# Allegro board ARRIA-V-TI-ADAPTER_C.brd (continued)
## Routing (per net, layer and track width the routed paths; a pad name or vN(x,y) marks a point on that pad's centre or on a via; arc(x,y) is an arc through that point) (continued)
ADC_A0P: length 187.7
  LAYER6 w0.112: v1(107.96,41.31) 108.44,41.8 112.46,41.8 168.78,98.12 168.78,117.22 168.49,117.51 163.7,117.51 163.58,117.63 163.58,117.94 163.7,118.06 168.49,118.06 168.78,118.35 168.78,118.94 168.49,119.23 163.82,119.23 163.69,119.36 163.69,119.66 163.82,119.79 168.49,119.79 168.78,120.08 168.78,120.67 168.49,120.96 164.12,120.96 164.01,121.07 164.01,121.41 164.12,121.52 168.49,121.52 168.78,121.81 168.78,122.4 168.49,122.69 164.12,122.69 164.01,122.8 164.01,123.13 164.12,123.25 168.49,123.25 168.78,123.54 168.78,124.12 168.49,124.41 164.12,124.41 164.01,124.53 164.01,124.86 164.12,124.97 168.49,124.97 168.78,125.26 168.78,127.84 183.44,142.5 183.44,144.65 v1(183.74,144.95)
  BOTTOM w0.114: v1(107.96,41.31) J3.K25 ; J1.94 183.54,143.9 183.44,144 183.44,144.65 v1(183.74,144.95)
ADC_A1N: length 200.6
  LAYER6 w0.112: v1(106.69,41.31) 107.17,40.83 114.36,40.83 170.81,97.28 170.81,101.79 171.11,102.08 175.64,102.08 175.77,102.21 175.77,102.51 175.64,102.64 171.11,102.64 170.81,102.93 170.81,103.52 171.11,103.81 175.84,103.81 175.97,103.93 175.97,104.24 175.84,104.36 171.11,104.36 170.81,104.65 170.81,105.24 171.11,105.53 175.84,105.53 175.97,105.66 175.97,105.96 175.84,106.09 171.11,106.09 170.81,106.38 170.81,106.97 171.11,107.26 175.84,107.26 175.97,107.39 175.97,107.69 175.84,107.82 171.11,107.82 170.81,108.11 170.81,108.7 171.11,108.99 175.84,108.99 175.97,109.11 175.97,109.42 175.84,109.55 171.11,109.55 170.81,109.84 170.81,110.42 171.11,110.71 175.84,110.71 175.97,110.84 175.97,111.15 175.84,111.27 171.11,111.27 170.81,111.56 170.81,127 180.47,136.65 180.82,136.65 180.94,136.76 180.94,136.92 181.06,137.05 181.37,137.05 181.49,136.92 181.49,136.76 181.61,136.65 183.26,136.65 184.64,138.03 184.64,140.41 v1(184.34,140.71)
  BOTTOM w0.114: v1(106.69,41.31) J3.J25 ; v1(184.34,140.71) 184.64,141.01 184.64,141.16 184.54,141.26 J1.90
ADC_A1P: length 200.6
  LAYER6 w0.112: v1(185.24,140.71) 184.94,140.41 184.94,137.9 183.39,136.35 180.59,136.35 171.12,126.87 171.12,111.69 171.23,111.58 175.97,111.58 176.28,111.27 176.28,110.72 175.97,110.41 171.23,110.41 171.12,110.3 171.12,109.96 171.23,109.85 175.97,109.85 176.28,109.55 176.28,108.99 175.97,108.68 171.23,108.68 171.12,108.57 171.12,108.24 171.23,108.12 175.97,108.12 176.28,107.82 176.28,107.26 175.97,106.96 171.23,106.96 171.12,106.84 171.12,106.51 171.23,106.4 175.97,106.4 176.28,106.09 176.28,105.53 175.97,105.23 171.23,105.23 171.12,105.12 171.12,104.78 171.23,104.67 175.97,104.67 176.28,104.36 176.28,103.81 175.97,103.5 171.23,103.5 171.12,103.39 171.12,103.05 171.23,102.94 175.77,102.94 176.07,102.64 176.07,102.08 175.77,101.77 171.23,101.77 171.12,101.66 171.12,97.16 114.49,40.53 107.17,40.53 v1(106.69,40.04)
  BOTTOM w0.114: J1.88 185.04,141.26 184.94,141.16 184.94,141.01 v1(185.24,140.71) ; v1(106.69,40.04) J3.J24
ADC_A2N: length 213.7
  LAYER6 w0.112: v1(185.84,144.95) 186.14,144.65 186.14,143.28 186.03,143.17 185.86,143.17 185.74,143.04 185.74,142.74 185.86,142.61 186.03,142.61 186.14,142.5 186.14,137.12 181.1,132.08 181.1,127.3 179.32,125.53 179.32,123.6 179.21,123.49 174.03,123.49 173.74,123.2 173.74,122.61 174.03,122.32 179.21,122.32 179.32,122.21 179.32,121.88 179.21,121.77 174.03,121.77 173.74,121.47 173.74,120.89 174.03,120.6 179.21,120.6 179.32,120.48 179.32,120.15 179.21,120.04 174.03,120.04 173.74,119.75 173.74,119.16 174.03,118.87 179.21,118.87 179.32,118.76 179.32,118.42 179.21,118.31 174.03,118.31 173.74,118.02 173.74,117.43 174.03,117.14 179.21,117.14 179.32,117.03 179.32,116.7 179.21,116.58 174.03,116.58 173.74,116.29 173.74,115.71 174.03,115.42 179.21,115.42 179.32,115.3 179.32,114.97 179.21,114.86 175.57,114.86 175.26,114.55 175.26,113.99 175.57,113.69 179.21,113.69 179.32,113.58 179.32,102.54 115.07,38.29 103.36,38.29 v1(102.88,38.77)
  BOTTOM w0.114: J1.84 186.04,143.9 186.14,144 186.14,144.65 v1(185.84,144.95) ; v1(102.88,38.77) J3.F23
ADC_A2P: length 213.7
  LAYER6 w0.112: v1(102.88,37.5) 103.36,37.99 115.2,37.99 179.63,102.41 179.63,113.7 179.34,113.99 175.69,113.99 175.56,114.12 175.56,114.42 175.69,114.55 179.34,114.55 179.63,114.84 179.63,115.43 179.34,115.72 174.15,115.72 174.04,115.83 174.04,116.17 174.15,116.28 179.34,116.28 179.63,116.57 179.63,117.16 179.34,117.45 174.15,117.45 174.04,117.56 174.04,117.89 174.15,118.01 179.34,118.01 179.63,118.3 179.63,118.88 179.34,119.17 174.15,119.17 174.04,119.29 174.04,119.62 174.15,119.73 179.34,119.73 179.63,120.02 179.63,120.61 179.34,120.9 174.15,120.9 174.04,121.01 174.04,121.35 174.15,121.46 179.34,121.46 179.63,121.75 179.63,122.34 179.34,122.63 174.15,122.63 174.04,122.74 174.04,123.08 174.15,123.19 179.34,123.19 179.63,123.48 179.63,125.4 181.41,127.18 181.41,131.95 186.44,136.99 186.44,144.65 v1(186.74,144.95)
  BOTTOM w0.114: J1.82 186.54,143.9 186.44,144 186.44,144.65 v1(186.74,144.95) ; v1(102.88,37.5) J3.F22
ADC_A3N: length 212.5
  LAYER6 w0.112: v1(187.34,140.71) 187.64,140.41 187.64,133.02 187.53,132.91 187.38,132.91 187.25,132.78 187.25,132.48 187.38,132.35 187.53,132.35 187.64,132.24 187.64,128.13 181.74,122.22 181.74,103.49 182.03,103.2 182.74,103.2 182.87,103.08 182.87,102.77 182.74,102.64 182.03,102.64 181.74,102.35 181.74,101.7 180.99,100.96 180.99,100.54 183.03,98.5 183.03,98.32 182.82,98.11 182.64,98.11 180.6,100.15 180.18,100.15 179.77,99.73 179.77,99.32 181.75,97.34 181.75,97.16 181.53,96.95 181.35,96.95 179.37,98.93 178.96,98.93 178.55,98.51 178.55,98.1 180.26,96.39 180.26,96.23 180.02,95.99 179.86,95.99 178.15,97.7 177.74,97.7 177.32,97.29 177.32,96.88 179.03,95.17 179.03,95.01 178.8,94.77 178.64,94.77 176.93,96.48 176.52,96.48 176.1,96.07 176.1,95.66 177.81,93.95 177.81,93.79 177.57,93.55 177.42,93.55 175.71,95.26 175.3,95.26 174.88,94.84 174.88,94.43 176.59,92.72 176.59,92.57 176.35,92.33 176.19,92.33 174.48,94.04 174.07,94.04 173.66,93.62 173.66,93.21 175.37,91.5 175.37,91.34 175.13,91.11 174.97,91.11 173.26,92.82 172.85,92.82 172.44,92.4 172.44,91.99 174.14,90.28 174.14,90.12 173.91,89.88 173.75,89.88 172.04,91.59 171.63,91.59 171.21,91.18 171.21,90.77 172.92,89.06 172.92,88.9 172.68,88.66 172.53,88.66 170.82,90.37 170.41,90.37 169.99,89.96 169.99,89.54 171.7,87.83 171.7,87.68 171.46,87.44 171.3,87.44 169.59,89.15 169.18,89.15 168.77,88.73 168.77,88.32 170.48,86.61 170.48,86.45 170.24,86.22 170.08,86.22 168.37,87.93 167.96,87.93 117.06,37.02 102.09,37.02 v1(101.61,37.5)
  BOTTOM w0.114: v1(101.61,37.5) J3.E22 ; J1.78 187.54,141.26 187.64,141.16 187.64,141.01 v1(187.34,140.71)
ADC_A3P: length 212.5
  LAYER6 w0.112: v1(188.24,140.71) 187.94,140.41 187.94,128 182.04,122.1 182.04,103.62 182.15,103.51 182.87,103.51 183.17,103.2 183.17,102.64 182.87,102.34 182.15,102.34 182.04,102.23 182.04,101.58 181.3,100.83 181.3,100.67 183.34,98.63 183.34,98.2 182.94,97.8 182.51,97.8 180.47,99.84 180.31,99.84 180.07,99.61 180.07,99.45 182.05,97.47 182.05,97.04 181.66,96.64 181.22,96.64 179.25,98.62 179.09,98.62 178.85,98.38 178.85,98.23 180.56,96.52 180.56,96.11 180.14,95.69 179.73,95.69 178.02,97.4 177.87,97.4 177.63,97.16 177.63,97 179.34,95.29 179.34,94.88 178.92,94.47 178.51,94.47 176.8,96.18 176.64,96.18 176.41,95.94 176.41,95.78 178.12,94.07 178.12,93.66 177.7,93.24 177.29,93.24 175.58,94.95 175.42,94.95 175.18,94.72 175.18,94.56 176.89,92.85 176.89,92.44 176.48,92.02 176.07,92.02 174.36,93.73 174.2,93.73 173.96,93.5 173.96,93.34 175.67,91.63 175.67,91.22 175.26,90.8 174.84,90.8 173.14,92.51 172.98,92.51 172.74,92.27 172.74,92.12 174.45,90.41 174.45,89.99 174.03,89.58 173.62,89.58 171.91,91.29 171.75,91.29 171.52,91.05 171.52,90.89 173.23,89.18 173.23,88.77 172.81,88.36 172.4,88.36 170.69,90.07 170.53,90.07 170.3,89.83 170.3,89.67 172.01,87.96 172.01,87.55 171.59,87.13 171.18,87.13 169.47,88.84 169.31,88.84 169.07,88.61 169.07,88.45 170.78,86.74 170.78,86.33 170.37,85.91 169.96,85.91 168.25,87.62 168.09,87.62 117.18,36.72 102.09,36.72 v1(101.61,36.23)
  BOTTOM w0.114: v1(101.61,36.23) J3.E21 ; J1.76 188.04,141.26 187.94,141.16 187.94,141.01 v1(188.24,140.71)
ADC_A4N: length 201.4
  LAYER6 w0.112: v1(100.34,20.99) 100.82,20.51 101.9,20.51 102.11,20.71 102.11,23.93 102.49,24.31 114.3,24.31 190.45,100.46 190.45,101.54 190.34,101.65 186.06,101.65 185.75,101.95 185.75,102.51 186.06,102.82 190.34,102.82 190.45,102.93 190.45,103.26 190.34,103.38 186.06,103.38 185.75,103.68 185.75,104.24 186.06,104.55 190.34,104.55 190.45,104.66 190.45,104.99 190.34,105.1 185.93,105.1 185.62,105.41 185.62,105.97 185.93,106.27 190.34,106.27 190.45,106.38 190.45,131.62 189.14,132.93 189.14,142.53 189.03,142.64 188.87,142.64 188.75,142.77 188.75,143.08 188.87,143.2 189.03,143.2 189.14,143.31 189.14,144.65 v1(188.84,144.95)
  BOTTOM w0.114: v1(100.34,20.99) J3.D9 ; J1.72 189.04,143.9 189.14,144 189.14,144.65 v1(188.84,144.95)
ADC_A4P: length 201.4
  LAYER6 w0.112: v1(100.34,19.72) 100.82,20.21 102.03,20.21 102.41,20.59 102.41,23.8 102.62,24 114.43,24 190.75,100.33 190.75,101.66 190.46,101.95 186.18,101.95 186.06,102.08 186.06,102.39 186.18,102.51 190.46,102.51 190.75,102.8 190.75,103.39 190.46,103.68 186.18,103.68 186.06,103.81 186.06,104.11 186.18,104.24 190.46,104.24 190.75,104.53 190.75,105.12 190.46,105.41 186.06,105.41 185.93,105.54 185.93,105.84 186.06,105.97 190.46,105.97 190.75,106.26 190.75,131.75 189.44,133.06 189.44,144.65 v1(189.74,144.95)
  BOTTOM w0.114: v1(100.34,19.72) J3.D8 ; v1(189.74,144.95) 189.44,144.65 189.44,144 189.54,143.9 J1.70
ADC_A5N: length 194.8
  LAYER6 w0.112: v1(104.15,22.26) 104.63,21.78 115.76,21.78 171.74,77.76 172.15,77.76 173.13,76.77 173.31,76.77 173.53,76.98 173.53,77.16 172.54,78.15 172.54,78.56 172.96,78.98 173.37,78.98 175.03,77.32 175.19,77.32 175.42,77.56 175.42,77.71 173.76,79.37 173.76,79.78 174.18,80.2 174.59,80.2 176.25,78.54 176.41,78.54 176.65,78.78 176.65,78.94 174.99,80.6 174.99,81.01 175.4,81.42 175.81,81.42 177.47,79.76 177.63,79.76 177.87,80 177.87,80.16 176.21,81.82 176.21,82.23 176.62,82.64 177.04,82.64 178.69,80.99 178.85,80.99 179.09,81.22 179.09,81.38 177.43,83.04 177.43,83.45 177.85,83.87 178.26,83.87 179.92,82.21 180.07,82.21 180.31,82.45 180.31,82.6 178.65,84.26 178.65,84.67 192.1,98.12 192.1,133.22 191.99,133.33 191.83,133.33 191.71,133.46 191.71,133.76 191.83,133.89 191.99,133.89 192.1,134 192.1,134.49 190.64,135.95 190.64,140.41 v1(190.34,140.71)
  BOTTOM w0.114: v1(104.15,22.26) J3.G10 ; J1.66 190.54,141.26 190.64,141.16 190.64,141.01 v1(190.34,140.71)
ADC_A5P: length 194.8
  LAYER6 w0.112: v1(104.15,20.99) 104.63,21.48 115.89,21.48 171.86,77.45 172.02,77.45 173.01,76.46 173.44,76.46 173.83,76.86 173.83,77.29 172.85,78.28 172.85,78.44 173.08,78.67 173.24,78.67 174.9,77.01 175.31,77.01 175.73,77.43 175.73,77.84 174.07,79.5 174.07,79.66 174.31,79.9 174.46,79.9 176.12,78.24 176.53,78.24 176.95,78.65 176.95,79.06 175.29,80.72 175.29,80.88 175.53,81.12 175.69,81.12 177.35,79.46 177.76,79.46 178.17,79.88 178.17,80.29 176.51,81.94 176.51,82.1 176.75,82.34 176.91,82.34 178.57,80.68 178.98,80.68 179.4,81.1 179.4,81.51 177.74,83.17 177.74,83.32 177.97,83.56 178.13,83.56 179.79,81.9 180.2,81.9 180.62,82.32 180.62,82.73 178.96,84.39 178.96,84.55 192.41,97.99 192.41,134.62 190.94,136.08 190.94,140.41 v1(191.24,140.71)
  BOTTOM w0.114: v1(104.15,20.99) J3.G9 ; J1.64 191.04,141.26 190.94,141.16 190.94,141.01 v1(191.24,140.71)
ADC_A6N: length 202.7
  LAYER6 w0.112: v1(105.42,19.72) 105.9,19.24 106.98,19.24 107.19,19.44 107.19,20.14 107.55,20.5 123.47,20.5 187.03,84.06 187.03,84.22 185.76,85.48 185.76,85.92 186.16,86.31 186.59,86.31 187.86,85.04 188.02,85.04 188.25,85.28 188.25,85.44 186.71,86.98 186.71,87.39 187.12,87.81 187.53,87.81 189.08,86.27 189.24,86.27 189.47,86.5 189.47,86.66 187.93,88.21 187.93,88.62 188.35,89.03 188.76,89.03 190.3,87.49 190.46,87.49 190.7,87.72 190.7,87.88 189.15,89.43 189.15,89.84 189.57,90.25 189.98,90.25 191.52,88.71 191.68,88.71 191.92,88.95 191.92,89.11 190.37,90.65 190.37,91.06 190.79,91.48 191.2,91.48 192.75,89.93 192.9,89.93 194.06,91.08 194.06,140.46 196.09,142.49 196.4,142.49 196.51,142.61 196.51,142.76 196.64,142.89 196.94,142.89 197.07,142.76 197.07,142.61 197.18,142.49 197.61,142.49 199.14,144.02 199.14,144.65 v1(198.84,144.95)
  BOTTOM w0.114: v1(198.84,144.95) 199.14,144.65 199.14,144 199.04,143.9 J1.52 ; v1(105.42,19.72) J3.H8
ADC_A6P: length 202.7
  LAYER6 w0.112: v1(199.74,144.95) 199.44,144.65 199.44,143.89 197.74,142.19 196.21,142.19 194.36,140.34 194.36,90.96 193.03,89.63 192.62,89.63 191.08,91.17 190.92,91.17 190.68,90.93 190.68,90.78 192.22,89.23 192.22,88.82 191.81,88.41 191.4,88.41 189.85,89.95 189.7,89.95 189.46,89.71 189.46,89.55 191,88.01 191,87.6 190.59,87.18 190.18,87.18 188.63,88.73 188.47,88.73 188.23,88.49 188.23,88.33 189.78,86.79 189.78,86.38 189.36,85.96 188.95,85.96 187.41,87.51 187.25,87.51 187.01,87.27 187.01,87.11 188.56,85.56 188.56,85.15 188.14,84.74 187.73,84.74 186.46,86.01 186.28,86.01 186.07,85.79 186.07,85.61 187.34,84.34 187.34,83.93 123.6,20.19 107.67,20.19 107.49,20.01 107.49,19.32 107.11,18.94 105.9,18.94 v1(105.42,18.45)
  BOTTOM w0.114: v1(199.74,144.95) 199.44,144.65 199.44,144 199.54,143.9 J1.50 ; v1(105.42,18.45) J3.H7
ADC_A7N: length 183.3
  LAYER6 w0.112: v1(200.34,140.71) 200.64,140.41 200.64,140.19 199.14,138.68 199.14,137.92 196.92,135.71 196.76,135.71 196.65,135.82 196.47,135.82 196.26,135.6 196.26,135.42 196.37,135.31 196.37,135.15 195.58,134.37 195.58,91.7 195.87,91.41 196.79,91.41 196.91,91.29 196.91,90.98 196.79,90.85 195.87,90.85 195.58,90.56 195.58,89.92 194.64,88.98 194.64,88.57 195.41,87.8 195.41,87.64 195.17,87.4 195.02,87.4 194.25,88.17 193.83,88.17 193.42,87.75 193.42,87.34 194.19,86.57 194.19,86.42 193.95,86.18 193.79,86.18 193.02,86.95 192.61,86.95 192.2,86.53 192.2,86.12 192.97,85.35 192.97,85.19 192.73,84.96 192.57,84.96 191.8,85.73 191.39,85.73 124.9,19.24 108.44,19.24 v1(107.96,19.72)
  BOTTOM w0.114: v1(200.34,140.71) 200.64,141.01 200.64,141.16 200.54,141.26 J1.46 ; v1(107.96,19.72) J3.K8
ADC_A7P: length 183.3
  LAYER6 w0.112: v1(201.24,140.71) 200.94,140.41 200.94,140.06 199.44,138.56 199.44,137.8 195.88,134.24 195.88,91.83 196,91.72 196.91,91.72 197.22,91.41 197.22,90.85 196.91,90.55 196,90.55 195.88,90.44 195.88,89.79 194.95,88.85 194.95,88.69 195.72,87.92 195.72,87.51 195.3,87.1 194.89,87.1 194.12,87.87 193.96,87.87 193.72,87.63 193.72,87.47 194.49,86.7 194.49,86.29 194.08,85.87 193.67,85.87 192.9,86.64 192.74,86.64 192.5,86.41 192.5,86.25 193.27,85.48 193.27,85.07 192.86,84.65 192.44,84.65 191.67,85.42 191.52,85.42 125.03,18.94 108.44,18.94 v1(107.96,18.45)
  BOTTOM w0.114: J1.44 201.04,141.26 200.94,141.16 200.94,141.01 v1(201.24,140.71) ; v1(107.96,18.45) J3.K7
ADC_A8N: length 184.9
  LAYER6 w0.112: v1(201.84,144.95) 202.14,144.65 202.14,142.9 202.03,142.79 201.88,142.79 201.75,142.66 201.75,142.36 201.88,142.23 202.03,142.23 202.14,142.12 202.14,137.55 200.61,136.02 200.61,134.62 199.21,133.22 199.21,86.39 130.8,17.97 107.17,17.97 v1(106.69,18.45)
  BOTTOM w0.114: v1(201.84,144.95) 202.14,144.65 202.14,144 202.04,143.9 J1.40 ; v1(106.69,18.45) J3.J7
ADC_A8P: length 184.9
  LAYER6 w0.112: v1(202.74,144.95) 202.44,144.65 202.44,137.42 200.91,135.89 200.91,134.49 199.52,133.1 199.52,86.26 130.92,17.67 107.17,17.67 v1(106.69,17.18)
  BOTTOM w0.114: J1.38 202.54,143.9 202.44,144 202.44,144.65 v1(202.74,144.95) ; v1(106.69,17.18) J3.J6
ADC_A9N: length 187.8
  LAYER6 w0.112: v1(203.34,140.71) 203.64,140.41 203.64,136.79 203.53,136.68 203.38,136.68 203.25,136.55 203.25,136.24 203.38,136.12 203.53,136.12 203.64,136.01 203.64,134.81 202.13,133.3 202.13,84.38 134.26,16.51 107.34,16.51 107.16,16.69 106.48,16.69 106.22,16.94 106.22,16.99 106.22,16.99 106.22,17.63 105.88,17.97 104.63,17.97 v1(104.15,18.45)
  BOTTOM w0.114: v1(203.34,140.71) 203.64,141.01 203.64,141.16 203.54,141.26 J1.34 ; v1(104.15,18.45) J3.G7
ADC_A9P: length 187.8
  LAYER6 w0.112: v1(204.24,140.71) 203.94,140.41 203.94,134.68 202.44,133.17 202.44,84.25 134.39,16.21 107.21,16.21 107.03,16.38 106.35,16.38 105.92,16.82 105.92,16.86 105.92,16.86 105.92,17.5 105.75,17.67 104.63,17.67 v1(104.15,17.18)
  BOTTOM w0.114: v1(204.24,140.71) 203.94,141.01 203.94,141.16 204.04,141.26 J1.32 ; v1(104.15,17.18) J3.G6
ADC_A10N: length 197.9
  LAYER6 w0.112: v1(204.84,144.95) 205.14,144.65 205.14,142.81 205.03,142.7 204.88,142.7 204.75,142.57 204.75,142.27 204.88,142.14 205.03,142.14 205.14,142.03 205.14,137.51 206.32,136.32 206.32,134.11 205.14,132.93 205.14,82.2 138.37,15.43 103.36,15.43 v1(102.88,15.91)
  BOTTOM w0.114: J1.28 205.04,143.9 205.14,144 205.14,144.65 v1(204.84,144.95) ; v1(102.88,15.91) J3.F5
ADC_A10P: length 197.9
  LAYER6 w0.112: v1(205.74,144.95) 205.44,144.65 205.44,137.63 206.63,136.45 206.63,133.99 205.44,132.8 205.44,82.08 138.49,15.13 103.36,15.13 v1(102.88,14.64)
  BOTTOM w0.114: J1.26 205.54,143.9 205.44,144 205.44,144.65 v1(205.74,144.95) ; v1(102.88,14.64) J3.F4
ADC_A11N: length 197.9
  LAYER6 w0.112: v1(101.61,13.37) 102.09,12.89 108.32,12.89 109.52,14.1 140.16,14.1 207.72,81.66 207.72,134.53 207.61,134.65 207.45,134.65 207.33,134.77 207.33,135.08 207.45,135.21 207.61,135.21 207.72,135.32 207.72,136.83 206.64,137.91 206.64,140.41 v1(206.34,140.71)
  BOTTOM w0.114: v1(206.34,140.71) 206.64,141.01 206.64,141.16 206.54,141.26 J1.22 ; v1(101.61,13.37) J3.E3
ADC_A11P: length 197.9
  LAYER6 w0.112: v1(101.61,12.1) 102.09,12.59 108.45,12.59 109.65,13.79 140.28,13.79 208.03,81.53 208.03,136.96 206.94,138.04 206.94,140.41 v1(207.24,140.71)
  BOTTOM w0.114: J1.20 207.04,141.26 206.94,141.16 206.94,141.01 v1(207.24,140.71) ; v1(101.61,12.1) J3.E2
ADC_B0N: length 210.6
  TOP w0.114: v1(206.34,132.84) 206.64,132.54 206.64,132.01 206.52,131.89 206.38,131.89 206.25,131.76 206.25,131.45 206.38,131.32 206.52,131.32 206.64,131.21 206.64,116.33 205.75,115.44 185.88,115.44 178.94,108.51 178.94,101.28 179.24,100.99 182.09,100.99 182.22,100.86 182.22,100.55 182.09,100.42 179.24,100.42 178.94,100.13 178.94,99.53 179.24,99.24 182.84,99.24 182.96,99.12 182.96,98.78 182.84,98.67 179.24,98.67 178.94,98.37 178.94,97.78 179.24,97.49 182.84,97.49 182.96,97.37 182.96,97.03 182.84,96.91 179.24,96.91 178.94,96.62 178.94,96.03 179.24,95.73 182.84,95.73 182.96,95.62 182.96,95.28 182.84,95.16 179.24,95.16 178.94,94.87 178.94,94.27 179.24,93.98 182.84,93.98 182.96,93.87 182.96,93.52 182.84,93.41 179.24,93.41 178.94,93.12 178.94,78.66 142.38,42.1 103.36,42.1 v1(102.88,42.58)
  BOTTOM w0.114: v1(102.88,42.58) J3.F26 ; v1(206.34,132.84) 206.64,133.14 206.64,135.42 206.54,135.52 J1.21
ADC_B0P: length 210.6
  TOP w0.114: v1(102.88,41.31) 103.36,41.8 142.51,41.8 179.25,78.54 179.25,92.99 179.36,93.1 182.97,93.1 183.26,93.4 183.26,93.99 182.97,94.29 179.36,94.29 179.25,94.4 179.25,94.74 179.36,94.86 182.97,94.86 183.26,95.15 183.26,95.75 182.97,96.04 179.36,96.04 179.25,96.15 179.25,96.5 179.36,96.61 182.97,96.61 183.26,96.9 183.26,97.5 182.97,97.79 179.36,97.79 179.25,97.91 179.25,98.25 179.36,98.36 182.97,98.36 183.26,98.65 183.26,99.25 182.97,99.54 179.36,99.54 179.25,99.66 179.25,100 179.36,100.11 182.22,100.11 182.52,100.42 182.52,100.99 182.22,101.3 179.36,101.3 179.25,101.41 179.25,108.38 186,115.14 205.88,115.14 206.94,116.2 206.94,132.54 v1(207.24,132.84)
  BOTTOM w0.114: J1.19 207.04,135.52 206.94,135.42 206.94,133.14 v1(207.24,132.84) ; v1(102.88,41.31) J3.F25
ADC_B1N: length 211.7
  TOP w0.114: v1(204.84,134.75) 205.14,134.45 205.14,134.03 205.02,133.92 204.88,133.92 204.75,133.79 204.75,133.47 204.88,133.34 205.02,133.34 205.14,133.23 205.14,117.73 204.76,117.35 183.85,117.35 171.02,104.52 171.02,100.1 171.31,99.81 173.69,99.81 173.81,99.68 173.81,99.36 173.69,99.24 171.31,99.24 171.02,98.94 171.02,98.35 171.31,98.06 175.35,98.06 175.46,97.94 175.46,97.6 175.35,97.48 171.31,97.48 171.02,97.19 171.02,96.6 171.31,96.3 175.35,96.3 175.46,96.19 175.46,95.85 175.35,95.73 171.31,95.73 171.02,95.44 171.02,94.84 171.31,94.55 175.35,94.55 175.46,94.44 175.46,94.09 175.35,93.98 171.31,93.98 171.02,93.69 171.02,93.09 171.31,92.8 175.35,92.8 175.46,92.68 175.46,92.34 175.35,92.23 171.31,92.23 171.02,91.93 171.02,76.07 138.33,43.38 106.43,43.38 106.22,43.59 106.22,44.3 105.88,44.64 102.09,44.64 v1(101.61,45.12)
  BOTTOM w0.114: J1.27 205.04,135.52 205.14,135.42 205.14,135.05 v1(204.84,134.75) ; v1(101.61,45.12) J3.E28
ADC_B1P: length 211.7
  TOP w0.114: v1(205.74,134.75) 205.44,134.45 205.44,117.6 204.88,117.04 183.97,117.04 171.32,104.39 171.32,100.23 171.44,100.11 173.81,100.11 174.12,99.81 174.12,99.24 173.81,98.93 171.44,98.93 171.32,98.82 171.32,98.48 171.44,98.36 175.48,98.36 175.77,98.07 175.77,97.47 175.48,97.18 171.44,97.18 171.32,97.07 171.32,96.72 171.44,96.61 175.48,96.61 175.77,96.32 175.77,95.72 175.48,95.43 171.44,95.43 171.32,95.31 171.32,94.97 171.44,94.86 175.48,94.86 175.77,94.56 175.77,93.97 175.48,93.67 171.44,93.67 171.32,93.56 171.32,93.22 171.44,93.1 175.48,93.1 175.77,92.81 175.77,92.21 175.48,91.92 171.44,91.92 171.32,91.81 171.32,75.95 138.46,43.08 106.3,43.08 105.92,43.46 105.92,44.17 105.75,44.34 102.09,44.34 v1(101.61,43.85)
  BOTTOM w0.114: v1(101.61,43.85) J3.E27 ; v1(205.74,134.75) 205.44,135.05 205.44,135.42 205.54,135.52 J1.25
ADC_B2N: length 204.1
  TOP w0.114: v1(106.69,45.12) 107.17,44.64 134.81,44.64 168.27,78.11 168.27,80.3 168.16,80.42 164.08,80.42 163.78,80.72 163.78,81.29 164.08,81.6 168.16,81.6 168.27,81.71 168.27,82.06 168.16,82.17 164.08,82.17 163.78,82.48 163.78,83.05 164.08,83.35 168.16,83.35 168.27,83.47 168.27,83.81 168.16,83.92 164.08,83.92 163.78,84.23 163.78,84.8 164.08,85.1 168.16,85.1 168.27,85.22 168.27,85.56 168.16,85.68 164.08,85.68 163.78,85.98 163.78,86.55 164.08,86.86 168.16,86.86 168.27,86.97 168.27,87.31 168.16,87.43 164.92,87.43 164.62,87.73 164.62,88.3 164.92,88.61 168.16,88.61 168.27,88.72 168.27,105.84 181.69,119.25 203.07,119.25 203.64,119.82 203.64,130.99 203.52,131.11 203.37,131.11 203.24,131.23 203.24,131.55 203.37,131.68 203.52,131.68 203.64,131.79 203.64,132.54 v1(203.34,132.84)
  BOTTOM w0.114: v1(203.34,132.84) 203.64,133.14 203.64,135.42 203.54,135.52 J1.33 ; v1(106.69,45.12) J3.J28
ADC_B2P: length 204.1
  TOP w0.114: v1(106.69,43.85) 107.17,44.34 134.94,44.34 168.58,77.98 168.58,80.43 168.29,80.72 164.21,80.72 164.08,80.85 164.08,81.17 164.21,81.29 168.29,81.29 168.58,81.59 168.58,82.18 168.29,82.48 164.21,82.48 164.08,82.6 164.08,82.92 164.21,83.05 168.29,83.05 168.58,83.34 168.58,83.94 168.29,84.23 164.21,84.23 164.08,84.36 164.08,84.67 164.21,84.8 168.29,84.8 168.58,85.09 168.58,85.69 168.29,85.98 164.21,85.98 164.08,86.11 164.08,86.43 164.21,86.55 168.29,86.55 168.58,86.85 168.58,87.44 168.29,87.73 165.05,87.73 164.92,87.86 164.92,88.18 165.05,88.31 168.29,88.31 168.58,88.6 168.58,105.71 181.81,118.95 203.2,118.95 203.94,119.69 203.94,132.54 v1(204.24,132.84)
  BOTTOM w0.114: v1(106.69,43.85) J3.J27 ; v1(204.24,132.84) 203.94,133.14 203.94,135.42 204.04,135.52 J1.31
ADC_B3N: length 194.1
  TOP w0.114: v1(107.96,46.39) 108.44,45.91 131,45.91 158.88,73.79 158.88,92.31 159.17,92.6 161.72,92.6 161.85,92.73 161.85,93.05 161.72,93.17 159.17,93.17 158.88,93.47 158.88,94.06 159.17,94.36 164.17,94.36 164.29,94.47 164.29,94.81 164.17,94.93 159.17,94.93 158.88,95.22 158.88,95.82 159.17,96.11 164.17,96.11 164.29,96.22 164.29,96.57 164.17,96.68 159.17,96.68 158.88,96.97 158.88,97.57 159.17,97.86 164.17,97.86 164.29,97.98 164.29,98.32 164.17,98.43 159.17,98.43 158.88,98.72 158.88,99.87 180.16,121.16 201.17,121.16 202.14,122.13 202.14,133.38 202.02,133.49 201.87,133.49 201.74,133.62 201.74,133.94 201.87,134.07 202.02,134.07 202.14,134.18 202.14,134.45 v1(201.84,134.75)
  BOTTOM w0.114: J1.39 202.04,135.52 202.14,135.42 202.14,135.05 v1(201.84,134.75) ; v1(107.96,46.39) J3.K29
ADC_B3P: length 194.1
  TOP w0.114: v1(202.74,134.75) 202.44,134.45 202.44,122 201.29,120.85 180.29,120.85 159.18,99.75 159.18,98.85 159.3,98.74 164.3,98.74 164.59,98.44 164.59,97.85 164.3,97.56 159.3,97.56 159.18,97.44 159.18,97.1 159.3,96.98 164.3,96.98 164.59,96.69 164.59,96.1 164.3,95.8 159.3,95.8 159.18,95.69 159.18,95.35 159.3,95.23 164.3,95.23 164.59,94.94 164.59,94.34 164.3,94.05 159.3,94.05 159.18,93.94 159.18,93.59 159.3,93.48 161.85,93.48 162.15,93.17 162.15,92.6 161.85,92.3 159.3,92.3 159.18,92.18 159.18,73.66 131.13,45.61 108.44,45.61 v1(107.96,45.12)
  BOTTOM w0.114: v1(107.96,45.12) J3.K28 ; v1(202.74,134.75) 202.44,135.05 202.44,135.42 202.54,135.52 J1.37
ADC_B4N: length 213.6
  TOP w0.114: v1(200.34,132.84) 200.64,132.54 200.64,123.93 199.77,123.06 177.75,123.06 156.08,101.4 156.08,96.77 155.97,96.66 155.82,96.66 155.69,96.53 155.69,96.21 155.82,96.09 155.97,96.09 156.08,95.97 156.08,95.58 155.97,95.47 153.07,95.47 152.78,95.17 152.78,94.58 153.07,94.28 155.97,94.28 156.08,94.17 156.08,93.83 155.97,93.71 153.07,93.71 152.78,93.42 152.78,92.82 153.07,92.53 155.97,92.53 156.08,92.42 156.08,92.07 155.97,91.96 153.07,91.96 152.78,91.67 152.78,91.07 153.07,90.78 155.97,90.78 156.08,90.66 156.08,90.32 155.97,90.21 153.07,90.21 152.78,89.91 152.78,89.32 153.07,89.03 155.97,89.03 156.08,88.91 156.08,88.57 155.97,88.45 153.07,88.45 152.78,88.16 152.78,87.57 153.07,87.27 155.97,87.27 156.08,87.16 156.08,86.82 155.97,86.7 153.07,86.7 152.78,86.41 152.78,85.81 153.07,85.52 155.97,85.52 156.08,85.41 156.08,85.06 155.97,84.95 153.07,84.95 152.78,84.66 152.78,84.06 153.07,83.77 155.97,83.77 156.08,83.65 156.08,83.31 155.97,83.2 153.07,83.2 152.78,82.9 152.78,82.31 153.07,82.02 155.97,82.02 156.08,81.9 156.08,81.56 155.97,81.44 154.13,81.44 153.82,81.14 153.82,80.57 154.13,80.26 155.97,80.26 156.08,80.15 156.08,75.31 127.94,47.17 106.25,47.17 105.92,46.84 105.92,46.16 105.66,45.91 103.36,45.91 v1(102.88,46.39)
  BOTTOM w0.114: v1(102.88,46.39) J3.F29 ; J1.45 200.54,135.52 200.64,135.42 200.64,133.14 v1(200.34,132.84)
ADC_B4P: length 213.6
  TOP w0.114: v1(201.24,132.84) 200.94,132.54 200.94,123.8 199.9,122.76 177.88,122.76 156.39,101.27 156.39,95.45 156.1,95.16 153.2,95.16 153.09,95.05 153.09,94.7 153.2,94.59 156.1,94.59 156.39,94.3 156.39,93.7 156.1,93.41 153.2,93.41 153.09,93.29 153.09,92.95 153.2,92.84 156.1,92.84 156.39,92.54 156.39,91.95 156.1,91.66 153.2,91.66 153.09,91.54 153.09,91.2 153.2,91.08 156.1,91.08 156.39,90.79 156.39,90.2 156.1,89.9 153.2,89.9 153.09,89.79 153.09,89.45 153.2,89.33 156.1,89.33 156.39,89.04 156.39,88.44 156.1,88.15 153.2,88.15 153.09,88.04 153.09,87.69 153.2,87.58 156.1,87.58 156.39,87.29 156.39,86.69 156.1,86.4 153.2,86.4 153.09,86.28 153.09,85.94 153.2,85.83 156.1,85.83 156.39,85.53 156.39,84.94 156.1,84.64 153.2,84.64 153.09,84.53 153.09,84.19 153.2,84.07 156.1,84.07 156.39,83.78 156.39,83.18 156.1,82.89 153.2,82.89 153.09,82.78 153.09,82.43 153.2,82.32 156.1,82.32 156.39,82.03 156.39,81.43 156.1,81.14 154.25,81.14 154.13,81.01 154.13,80.7 154.25,80.57 156.1,80.57 156.39,80.28 156.39,75.18 128.07,46.86 106.37,46.86 106.22,46.71 106.22,46.04 105.79,45.61 103.36,45.61 v1(102.88,45.12)
  BOTTOM w0.114: v1(201.24,132.84) 200.94,133.14 200.94,135.42 201.04,135.52 J1.43 ; v1(102.88,45.12) J3.F28
ADC_B5N: length 207.1
  TOP w0.114: v1(198.84,134.75) 199.14,134.45 199.14,133.97 199.02,133.85 198.87,133.85 198.74,133.73 198.74,133.41 198.87,133.28 199.02,133.28 199.14,133.17 199.14,132.13 198.76,131.75 195,131.75 194.69,131.44 194.69,130.61 195,130.3 199.01,130.3 199.14,130.18 199.14,129.59 199.01,129.46 192.28,129.46 191.97,129.16 191.97,128.45 192.28,128.14 199.01,128.14 199.14,128.02 199.14,127.43 199.01,127.3 192.15,127.3 191.85,127 191.85,126.16 192.15,125.86 199.01,125.86 199.14,125.73 199.14,125.09 199.01,124.97 176.35,124.97 174.96,123.58 174.8,123.58 174.1,124.28 173.68,124.28 173.26,123.86 173.26,123.44 173.96,122.74 173.96,122.58 173.72,122.34 173.56,122.34 172.86,123.04 172.44,123.04 172.02,122.62 172.02,122.2 172.72,121.5 172.72,121.34 172.48,121.1 172.32,121.1 171.62,121.8 171.2,121.8 170.78,121.38 170.78,120.96 171.48,120.26 171.48,120.1 171.24,119.86 171.08,119.86 170.38,120.56 169.96,120.56 169.54,120.14 169.54,119.72 170.24,119.02 170.24,118.86 170,118.62 169.84,118.62 169.14,119.32 168.72,119.32 168.3,118.9 168.3,118.48 169,117.78 169,117.62 168.76,117.38 168.6,117.38 167.9,118.08 167.48,118.08 167.06,117.66 167.06,117.24 167.76,116.54 167.76,116.38 167.52,116.14 167.36,116.14 166.66,116.84 166.24,116.84 165.82,116.42 165.82,116 166.52,115.3 166.52,115.14 165.91,114.53 165.75,114.53 164.92,115.36 164.51,115.36 164.09,114.94 164.09,114.52 164.92,113.69 164.92,113.53 149.1,97.71 149.1,73.53 124.02,48.45 107.17,48.45 v1(106.69,48.93)
  BOTTOM w0.114: v1(198.84,134.75) 199.14,135.05 199.14,135.42 199.04,135.52 J1.51 ; v1(106.69,48.93) J3.J31
ADC_B5P: length 207.1
  TOP w0.114: v1(199.74,134.75) 199.44,134.45 199.44,132.01 198.88,131.44 195.12,131.44 195,131.32 195,130.73 195.12,130.61 199.14,130.61 199.44,130.3 199.44,129.46 199.14,129.16 192.41,129.16 192.28,129.03 192.28,128.57 192.41,128.45 199.14,128.45 199.44,128.14 199.44,127.31 199.14,127 192.28,127 192.15,126.87 192.15,126.29 192.28,126.16 199.14,126.16 199.44,125.86 199.44,124.97 199.14,124.66 176.48,124.66 175.09,123.27 174.67,123.27 173.97,123.98 173.81,123.98 173.57,123.73 173.57,123.57 174.27,122.87 174.27,122.45 173.85,122.03 173.43,122.03 172.73,122.74 172.57,122.74 172.33,122.49 172.33,122.33 173.03,121.63 173.03,121.21 172.61,120.79 172.19,120.79 171.49,121.5 171.33,121.5 171.09,121.25 171.09,121.09 171.79,120.39 171.79,119.97 171.37,119.55 170.95,119.55 170.25,120.26 170.09,120.26 169.85,120.01 169.85,119.85 170.55,119.15 170.55,118.73 170.13,118.31 169.71,118.31 169.01,119.02 168.85,119.02 168.61,118.77 168.61,118.61 169.31,117.91 169.31,117.49 168.89,117.07 168.47,117.07 167.77,117.77 167.61,117.77 167.37,117.53 167.37,117.37 168.07,116.67 168.07,116.25 167.65,115.83 167.23,115.83 166.53,116.53 166.37,116.53 166.13,116.29 166.13,116.13 166.83,115.43 166.83,115.01 166.04,114.22 165.63,114.22 164.8,115.05 164.63,115.05 164.39,114.81 164.39,114.65 165.22,113.82 165.22,113.4 149.4,97.59 149.4,73.41 124.14,48.15 107.17,48.15 v1(106.69,47.66)
  BOTTOM w0.114: v1(199.74,134.75) 199.44,135.05 199.44,135.42 199.54,135.52 J1.49 ; v1(106.69,47.66) J3.J30
ADC_B6N: length 186.7
  TOP w0.114: v1(107.96,50.2) 108.44,49.72 121.6,49.72 146.3,74.42 146.3,86.78 146.19,86.89 142.93,86.89 142.62,87.2 142.62,87.77 142.93,88.08 146.19,88.08 146.3,88.19 146.3,88.53 146.19,88.65 142.41,88.65 142.11,88.94 142.11,89.53 142.41,89.83 146.19,89.83 146.3,89.94 146.3,90.28 146.19,90.4 142.41,90.4 142.11,90.69 142.11,91.29 142.41,91.58 146.19,91.58 146.3,91.69 146.3,92.04 146.19,92.15 142.41,92.15 142.11,92.44 142.11,93.04 142.41,93.33 146.19,93.33 146.3,93.45 146.3,93.79 146.19,93.9 142.41,93.9 142.11,94.2 142.11,94.79 142.41,95.09 146.19,95.09 146.3,95.2 146.3,95.54 146.19,95.66 142.41,95.66 142.11,95.95 142.11,96.55 142.41,96.84 146.19,96.84 146.3,96.95 146.3,100.84 172.34,126.87 187.34,126.87 187.46,126.99 187.46,127.15 187.58,127.28 187.9,127.28 188.03,127.15 188.03,126.99 188.14,126.87 188.8,126.87 189.11,127.19 189.11,127.89 v1(188.86,128.14)
  BOTTOM w0.114: v1(188.86,128.14) 189.14,128.43 189.14,135.42 189.04,135.52 J1.71 ; v1(107.96,50.2) J3.K32
ADC_B6P: length 186.7
  TOP w0.114: v1(189.73,128.14) 189.42,127.83 189.42,127.06 188.93,126.57 172.47,126.57 146.61,100.71 146.61,96.83 146.32,96.53 142.53,96.53 142.42,96.42 142.42,96.08 142.53,95.96 146.32,95.96 146.61,95.67 146.61,95.07 146.32,94.78 142.53,94.78 142.42,94.67 142.42,94.32 142.53,94.21 146.32,94.21 146.61,93.92 146.61,93.32 146.32,93.03 142.53,93.03 142.42,92.91 142.42,92.57 142.53,92.46 146.32,92.46 146.61,92.16 146.61,91.57 146.32,91.28 142.53,91.28 142.42,91.16 142.42,90.82 142.53,90.7 146.32,90.7 146.61,90.41 146.61,89.82 146.32,89.52 142.53,89.52 142.42,89.41 142.42,89.07 142.53,88.95 146.32,88.95 146.61,88.66 146.61,88.06 146.32,87.77 143.05,87.77 142.93,87.64 142.93,87.33 143.05,87.2 146.32,87.2 146.61,86.91 146.61,74.3 121.73,49.42 108.44,49.42 v1(107.96,48.93)
  BOTTOM w0.114: v1(189.73,128.14) 189.44,128.43 189.44,135.42 189.54,135.52 J1.69 ; v1(107.96,48.93) J3.K31
ADC_B7N: length 211.1
  TOP w0.114: v1(101.61,41.31) 102.09,40.83 145.86,40.83 187.64,82.61 187.64,84.84 187.52,84.95 184.11,84.95 183.81,85.26 183.81,85.83 184.11,86.13 187.52,86.13 187.64,86.25 187.64,86.59 187.52,86.7 184.95,86.7 184.66,87 184.66,87.59 184.95,87.88 187.52,87.88 187.64,88 187.64,88.34 187.52,88.46 184.95,88.46 184.66,88.75 184.66,89.34 184.95,89.64 187.52,89.64 187.64,89.75 187.64,90.09 187.52,90.21 184.95,90.21 184.66,90.5 184.66,91.1 184.95,91.39 187.52,91.39 187.64,91.5 187.64,103.4 187.52,103.52 184.19,103.52 183.9,103.81 183.9,104.41 184.19,104.7 187.52,104.7 187.64,104.81 187.64,105.16 187.52,105.27 184.19,105.27 183.9,105.56 183.9,106.16 184.19,106.45 187.52,106.45 187.64,106.57 187.64,106.91 187.52,107.02 184.19,107.02 183.9,107.32 183.9,107.91 184.19,108.21 187.52,108.21 187.64,108.32 187.64,108.66 187.52,108.78 184.19,108.78 183.9,109.07 183.9,109.67 184.19,109.96 187.52,109.96 187.64,110.07 187.64,111.58 187.52,111.7 187.38,111.7 187.25,111.82 187.25,112.14 187.38,112.27 187.52,112.27 187.64,112.38 187.64,113.13 v1(187.36,113.41)
  BOTTOM w0.114: J1.77 187.54,135.52 187.64,135.42 187.64,113.69 v1(187.36,113.41) ; v1(101.61,41.31) J3.E25
ADC_B7P: length 211.1
  TOP w0.114: v1(101.61,40.04) 102.09,40.53 145.99,40.53 187.94,82.48 187.94,84.96 187.65,85.26 184.24,85.26 184.11,85.38 184.11,85.7 184.24,85.83 187.65,85.83 187.94,86.12 187.94,86.72 187.65,87.01 185.08,87.01 184.96,87.12 184.96,87.46 185.08,87.58 187.65,87.58 187.94,87.87 187.94,88.47 187.65,88.76 185.08,88.76 184.96,88.87 184.96,89.22 185.08,89.33 187.65,89.33 187.94,89.62 187.94,90.22 187.65,90.51 185.08,90.51 184.96,90.63 184.96,90.97 185.08,91.08 187.65,91.08 187.94,91.38 187.94,103.53 187.65,103.82 184.32,103.82 184.2,103.94 184.2,104.28 184.32,104.4 187.65,104.4 187.94,104.69 187.94,105.28 187.65,105.58 184.32,105.58 184.2,105.69 184.2,106.03 184.32,106.15 187.65,106.15 187.94,106.44 187.94,107.04 187.65,107.33 184.32,107.33 184.2,107.44 184.2,107.79 184.32,107.9 187.65,107.9 187.94,108.19 187.94,108.79 187.65,109.08 184.32,109.08 184.2,109.2 184.2,109.54 184.32,109.65 187.65,109.65 187.94,109.95 187.94,113.13 v1(188.23,113.41)
  BOTTOM w0.114: v1(188.23,113.41) 187.94,113.69 187.94,135.42 188.04,135.52 J1.75 ; v1(101.61,40.04) J3.E24
ADC_B8N: length 268.9
  LAYER3 w0.112: v1(185.84,134.75) 186.14,135.05 186.14,135.59 186.56,136.02 187.45,136.02 187.83,135.64 187.83,130.73 188.09,130.48 192.79,130.48 193.09,130.17 193.09,129.34 192.79,129.03 188.09,129.03 187.96,128.91 187.96,126.03 188.09,125.91 193.15,125.91 193.46,125.6 193.46,124.71 193.15,124.41 186.82,124.41 186.51,124.71 186.51,130.81 186.39,130.94 185.93,130.94 185.8,130.81 185.8,124.71 185.5,124.41 184.66,124.41 184.35,124.71 184.35,130.68 184.23,130.81 183.64,130.81 183.51,130.68 183.51,124.71 183.21,124.41 182.25,124.41 181.94,124.71 181.94,130.81 181.81,130.94 181.38,130.94 181.25,130.81 181.25,124.7 180.96,124.41 179.57,124.41 179.28,124.7 179.28,125.73 179.16,125.86 178.85,125.86 178.72,125.73 178.72,124.7 178.43,124.41 177.84,124.41 177.55,124.7 177.55,125.73 177.43,125.86 177.12,125.86 177,125.73 177,124.7 176.71,124.41 176.12,124.41 175.83,124.7 175.83,125.06 175.72,125.17 175.38,125.17 175.27,125.06 175.27,124.7 174.98,124.41 174.39,124.41 174.1,124.7 174.1,125.06 173.99,125.17 173.65,125.17 173.54,125.06 173.54,124.7 173.25,124.41 172.66,124.41 172.37,124.7 172.37,125.06 172.26,125.17 171.93,125.17 171.81,125.06 171.81,124.7 171.52,124.41 170.94,124.41 170.65,124.7 170.65,125.06 170.53,125.17 170.2,125.17 170.09,125.06 170.09,124.7 169.8,124.41 169.21,124.41 168.92,124.7 168.92,125.06 168.81,125.17 168.47,125.17 168.36,125.06 168.36,124.7 168.07,124.41 167.15,124.41 166.86,124.7 166.86,125.19 166.75,125.3 166.42,125.3 166.3,125.19 166.3,124.7 166.01,124.41 165.43,124.41 165.14,124.7 165.14,125.19 165.02,125.3 164.69,125.3 164.58,125.19 164.58,124.7 164.29,124.41 163.7,124.41 163.41,124.7 163.41,125.19 163.3,125.3 162.96,125.3 162.85,125.19 162.85,124.7 162.56,124.41 161.97,124.41 161.68,124.7 161.68,125.19 161.57,125.3 161.23,125.3 161.12,125.19 161.12,124.7 160.83,124.41 58.98,124.41 58.62,124.76 58.29,124.76 58.17,124.65 58.17,124.34 57.88,124.05 57.3,124.05 57.01,124.34 57.01,124.65 56.89,124.76 56.56,124.76 56.45,124.65 56.45,124.34 56.16,124.05 55.57,124.05 55.28,124.34 55.28,124.65 55.17,124.76 54.78,124.76 54.43,124.41 46.86,124.41 31.04,108.59 31.04,101.45 31.32,101.17 v1(31.32,100.74)
  BOTTOM w0.114: v1(31.32,100.74) 31.32,100.32 31.04,100.04 31.04,99.19 32.81,97.41 32.81,97 32.91,96.9 J4.88 ; v1(185.84,134.75) 186.14,135.05 186.14,135.42 186.04,135.52 J1.83
ADC_B8P: length 268.9
  LAYER3 w0.112: v1(30.45,100.74) 30.45,101.17 30.73,101.45 30.73,108.71 46.74,124.71 54.3,124.71 54.66,125.07 55.29,125.07 55.58,124.78 55.58,124.47 55.69,124.36 56.03,124.36 56.14,124.47 56.14,124.78 56.43,125.07 57.02,125.07 57.31,124.78 57.31,124.47 57.42,124.36 57.76,124.36 57.87,124.47 57.87,124.78 58.16,125.07 58.75,125.07 59.1,124.71 160.71,124.71 160.82,124.83 160.82,125.31 161.11,125.6 161.7,125.6 161.99,125.31 161.99,124.83 162.1,124.71 162.43,124.71 162.54,124.83 162.54,125.31 162.83,125.6 163.42,125.6 163.71,125.31 163.71,124.83 163.82,124.71 164.16,124.71 164.27,124.83 164.27,125.31 164.56,125.6 165.15,125.6 165.44,125.31 165.44,124.83 165.55,124.71 165.89,124.71 166,124.83 166,125.31 166.29,125.6 166.88,125.6 167.17,125.31 167.17,124.83 167.28,124.71 167.94,124.71 168.06,124.83 168.06,125.19 168.35,125.48 168.93,125.48 169.22,125.19 169.22,124.83 169.34,124.71 169.67,124.71 169.78,124.83 169.78,125.19 170.07,125.48 170.66,125.48 170.95,125.19 170.95,124.83 171.06,124.71 171.4,124.71 171.51,124.83 171.51,125.19 171.8,125.48 172.39,125.48 172.68,125.19 172.68,124.83 172.79,124.71 173.13,124.71 173.24,124.83 173.24,125.19 173.53,125.48 174.12,125.48 174.41,125.19 174.41,124.83 174.52,124.71 174.85,124.71 174.96,124.83 174.96,125.19 175.25,125.48 175.84,125.48 176.13,125.19 176.13,124.83 176.24,124.71 176.58,124.71 176.69,124.83 176.69,125.86 177,126.16 177.55,126.16 177.86,125.86 177.86,124.83 177.97,124.71 178.31,124.71 178.42,124.83 178.42,125.86 178.72,126.16 179.28,126.16 179.59,125.86 179.59,124.83 179.7,124.71 180.83,124.71 180.95,124.83 180.95,130.94 181.25,131.24 181.94,131.24 182.25,130.94 182.25,124.84 182.37,124.71 183.08,124.71 183.21,124.84 183.21,130.81 183.52,131.11 184.35,131.11 184.66,130.81 184.66,124.84 184.78,124.71 185.37,124.71 185.5,124.84 185.5,130.94 185.8,131.24 186.51,131.24 186.82,130.94 186.82,124.84 186.94,124.71 193.03,124.71 193.15,124.84 193.15,125.48 193.03,125.6 187.96,125.6 187.66,125.91 187.66,129.03 187.96,129.34 192.66,129.34 192.79,129.46 192.79,130.05 192.66,130.18 187.96,130.18 187.53,130.61 187.53,132.94 187.42,133.06 187.01,133.06 186.88,133.18 186.88,133.49 187.01,133.62 187.42,133.62 187.53,133.73 187.53,135.51 187.33,135.71 186.69,135.71 186.44,135.47 186.44,135.05 v1(186.74,134.75)
  BOTTOM w0.114: J4.86 32.41,96.9 32.51,97 32.51,97.29 30.73,99.06 30.73,100.04 30.45,100.32 v1(30.45,100.74) ; J1.81 186.54,135.52 186.44,135.42 186.44,135.05 v1(186.74,134.75)
ADC_B9N: length 268.4
  BOTTOM w0.114: J4.82 31.41,95.07 31.31,94.97 31.31,94.86 31.63,94.54 42.16,94.54 42.37,94.74 42.37,97 42.21,97.15 42.21,97.72 42.37,97.88 42.37,98.45 42.21,98.6 42.21,99.17 42.37,99.32 42.37,99.9 42.21,100.05 42.21,100.62 42.37,100.77 42.37,101.34 42.21,101.5 42.21,102.07 42.37,102.22 42.37,102.79 42.21,102.94 42.21,103.51 42.37,103.67 42.37,104.7 42.25,104.81 39.99,104.81 39.7,105.11 39.7,105.7 39.99,105.99 44.92,105.99 45.03,106.11 45.03,106.45 44.92,106.57 42.66,106.57 42.37,106.86 42.37,108.17 42.11,108.43 42.11,109 42.37,109.25 42.37,109.82 42.11,110.08 42.11,110.65 42.37,110.9 42.37,121.28 42.67,121.59 43.43,121.59 43.74,121.28 43.74,110.74 43.87,110.62 44.45,110.62 44.58,110.74 44.58,121.28 44.88,121.59 45.8,121.59 46.1,121.28 46.1,110.74 46.23,110.62 46.81,110.62 46.94,110.74 46.94,121.28 47.24,121.59 47.95,121.59 48.26,121.28 48.26,111.87 48.39,111.75 49.1,111.75 49.23,111.87 49.23,121.28 49.53,121.59 182.42,121.59 184.64,123.81 184.64,135.42 184.54,135.52 J1.89
ADC_B9P: length 268.4
  BOTTOM w0.114: J4.80 30.91,95.07 31.01,94.97 31.01,94.73 31.5,94.23 42.29,94.23 42.67,94.62 42.67,102.33 42.74,102.4 42.74,103.1 42.67,103.16 42.67,104.83 42.38,105.12 40.12,105.12 40,105.23 40,105.58 40.12,105.69 45.05,105.69 45.34,105.98 45.34,106.58 45.05,106.87 42.79,106.87 42.67,106.99 42.67,121.16 42.8,121.28 43.31,121.28 43.43,121.16 43.43,110.62 43.74,110.31 44.58,110.31 44.88,110.62 44.88,121.16 45.01,121.28 45.67,121.28 45.8,121.16 45.8,110.62 46.1,110.31 46.94,110.31 47.24,110.62 47.24,121.16 47.37,121.28 47.83,121.28 47.96,121.16 47.96,111.75 48.26,111.44 49.22,111.44 49.53,111.75 49.53,121.16 49.66,121.28 182.55,121.28 184.94,123.68 184.94,135.42 185.04,135.52 J1.87
ADC_B10N: length 268.8
  LAYER3 w0.112: v1(19.56,100.81) 19.98,100.81 20.26,101.09 20.5,101.09 20.79,101.38 20.79,120.59 20.89,120.69 20.89,121.32 20.79,121.42 20.79,122.41 20.9,122.53 21.58,122.53 21.87,122.82 21.87,123.4 21.58,123.69 19.82,123.69 19.71,123.81 19.71,124.14 19.82,124.25 20.5,124.25 20.79,124.54 20.79,125.38 19.81,126.36 19.81,128.52 20.45,129.16 21.19,129.16 21.48,129.45 21.48,130.77 21.59,130.88 21.93,130.88 22.04,130.77 22.04,129.45 22.33,129.16 22.71,129.16 23.02,128.85 23.58,128.85 23.88,129.16 23.88,134.51 23.99,134.62 24.33,134.62 24.44,134.51 24.44,129.16 24.74,128.85 25.3,128.85 25.61,129.16 25.61,134.51 25.72,134.62 26.06,134.62 26.17,134.51 26.17,129.16 26.47,128.85 27.03,128.85 27.34,129.16 27.34,134.51 27.45,134.62 27.78,134.62 27.89,134.51 27.89,129.16 28.2,128.85 28.76,128.85 29.06,129.16 29.06,134.51 29.17,134.62 29.51,134.62 29.62,134.51 29.62,133.25 29.93,132.94 30.48,132.94 30.79,133.25 30.79,134.51 30.9,134.62 177.55,134.62 178.94,136.02 181.81,136.02 182.28,135.55 182.28,135.39 182.17,135.29 182.17,135.11 182.39,134.89 182.57,134.89 182.68,135 182.83,135 183.14,134.69 183.14,134.22 183.03,134.11 182.87,134.11 182.74,133.98 182.74,133.68 182.87,133.55 183.03,133.55 183.14,133.44 183.14,132.85 182.86,132.56 v1(182.86,131.79)
  BOTTOM w0.114: J1.95 183.04,135.52 183.14,135.42 183.14,134.87 183.14,132.71 183.14,132.49 182.86,132.21 v1(182.86,131.79) ; v1(19.56,100.81) 19.98,100.81 20.26,101.09 20.49,101.09 20.57,101.01 20.57,100.58 22.86,98.3 22.86,94.55 23.36,94.06 29.52,94.06 29.81,94.35 29.81,94.97 29.91,95.07 J4.76
ADC_B10P: length 268.8
  LAYER3 w0.112: v1(19.56,101.68) 19.98,101.68 20.26,101.4 20.38,101.4 20.49,101.51 20.49,115.94 19.84,116.59 19.84,117.15 20.49,117.8 20.49,118.36 19.84,119.01 19.84,119.57 20.49,120.22 20.49,122.54 20.78,122.83 21.46,122.83 21.57,122.94 21.57,123.28 21.46,123.39 19.7,123.39 19.41,123.68 19.41,124.27 19.7,124.56 20.38,124.56 20.49,124.67 20.49,125.26 19.51,126.24 19.51,128.65 20.32,129.46 21.06,129.46 21.17,129.58 21.17,130.89 21.46,131.18 22.05,131.18 22.34,130.89 22.34,129.58 22.45,129.46 22.84,129.46 23.14,129.16 23.45,129.16 23.58,129.29 23.58,134.63 23.87,134.92 24.45,134.92 24.74,134.63 24.74,129.29 24.87,129.16 25.18,129.16 25.3,129.29 25.3,134.63 25.59,134.92 26.18,134.92 26.47,134.63 26.47,129.29 26.6,129.16 26.9,129.16 27.03,129.29 27.03,134.63 27.32,134.92 27.91,134.92 28.2,134.63 28.2,129.29 28.33,129.16 28.63,129.16 28.76,129.29 28.76,134.63 29.05,134.92 29.64,134.92 29.93,134.63 29.93,133.38 30.05,133.25 30.36,133.25 30.48,133.38 30.48,134.63 30.77,134.92 177.42,134.92 178.82,136.32 181.94,136.32 183.44,134.82 183.44,132.84 183.73,132.56 183.73,132.22 183.73,132.22 v1(183.73,131.79)
  BOTTOM w0.114: J1.93 183.54,135.52 183.44,135.42 183.44,135 183.44,132.84 183.44,132.84 183.44,132.49 183.73,132.21 v1(183.73,131.79) ; v1(19.56,101.68) 19.98,101.68 20.26,101.4 20.62,101.4 20.88,101.14 20.88,100.71 23.16,98.42 23.16,94.68 23.48,94.36 29.39,94.36 29.51,94.48 29.51,94.97 29.41,95.07 J4.74
ADC_B11N: length 269.2
  BOTTOM w0.114: J1.101 181.54,138.16 181.64,138.26 181.64,138.38 181.52,138.49 173.92,138.49 163.45,128.02 68.18,128.02 68.08,127.91 67.41,127.91 67.31,128.02 66.48,128.02 66.28,127.81 65.7,127.81 65.5,128.02 64.93,128.02 64.73,127.81 64.16,127.81 63.95,128.02 62.94,128.02 62.69,127.76 62.07,127.76 61.81,128.02 61.24,128.02 60.96,127.74 60.39,127.74 60.11,128.02 59.54,128.02 59.26,127.74 58.69,127.74 58.41,128.02 57.44,128.02 57.31,127.89 56.13,127.89 56,128.02 41.33,128.02 41.04,128.31 41.04,128.99 40.92,129.11 40.58,129.11 40.46,128.99 40.46,128.31 40.17,128.02 33.78,128.02 28.31,122.54 28.31,122.17 28.31,114.84 28.02,114.55 23.41,114.55 23.29,114.43 23.29,114.09 23.41,113.98 33.03,113.98 33.33,113.69 33.33,113.09 33.03,112.8 23.41,112.8 23.29,112.68 23.29,112.34 23.41,112.23 33.03,112.23 33.33,111.93 33.33,111.34 33.03,111.04 23.41,111.04 23.29,110.93 23.29,110.59 23.41,110.47 33.03,110.47 33.33,110.18 33.33,109.58 33.03,109.29 23.41,109.29 23.29,109.18 23.29,108.83 23.41,108.72 33.03,108.72 33.33,108.43 33.33,107.83 33.03,107.54 28.42,107.54 28.31,107.42 28.31,97 28.41,96.9 J4.70
ADC_B11P: length 269.2
  BOTTOM w0.114: J4.68 27.91,96.9 28,97 28,107.55 28.3,107.84 32.91,107.84 33.02,107.96 33.02,108.3 32.91,108.42 23.28,108.42 22.99,108.71 22.99,109.3 23.28,109.6 32.91,109.6 33.02,109.71 33.02,110.05 32.91,110.17 23.28,110.17 22.99,110.46 22.99,111.06 23.28,111.35 32.91,111.35 33.02,111.46 33.02,111.81 32.91,111.92 23.28,111.92 22.99,112.21 22.99,112.81 23.28,113.1 32.91,113.1 33.02,113.22 33.02,113.56 32.91,113.67 23.28,113.67 22.99,113.97 22.99,114.56 23.28,114.85 27.89,114.85 28,114.97 28,122.3 28.01,122.3 28.01,122.67 33.66,128.32 40.05,128.32 40.16,128.44 40.16,129.12 40.45,129.41 41.05,129.41 41.34,129.12 41.34,128.44 41.46,128.32 56.13,128.32 56.25,128.19 57.18,128.19 57.31,128.32 58.78,128.32 58.89,128.42 59.61,128.42 59.71,128.32 163.32,128.32 173.8,138.79 181.65,138.79 181.94,138.5 181.94,138.26 182.04,138.16 J1.99
CLKOUTAN: length 197
  TOP w0.114: v1(105.42,15.91) 105.42,15.56 105.55,15.43 105.79,15.43 105.92,15.56 105.92,16.26 105.79,16.38 99.69,16.38 98.3,17.78 98.3,47.04 103.51,52.25 118.11,52.25 138.3,72.44 138.3,97.21 170.43,129.34 188.98,129.34 196.34,136.7 196.34,136.86 196.23,136.97 196.23,137.15 196.45,137.38 196.63,137.38 196.74,137.26 196.9,137.26 197.64,138 197.64,140.41 v1(197.34,140.71)
  BOTTOM w0.114: v1(105.42,15.91) J3.H5 ; v1(197.34,140.71) 197.64,141.01 197.64,141.16 197.54,141.26 J1.58
CLKOUTAP: length 197
  TOP w0.114: v1(198.24,140.71) 197.94,140.41 197.94,137.87 189.1,129.03 170.56,129.03 138.61,97.08 138.61,72.31 118.24,51.94 103.63,51.94 98.6,46.91 98.6,17.91 99.82,16.69 105.92,16.69 106.22,16.38 106.22,15.43 105.92,15.13 105.55,15.13 105.42,15 v1(105.42,14.64)
  BOTTOM w0.114: v1(105.42,14.64) J3.H4 ; J1.56 198.04,141.26 197.94,141.16 197.94,141.01 v1(198.24,140.71)
CONN_G0: length 193.8
  LAYER3 w0.124: v1(29.41,91.62) 29.08,91.95 29.08,94.37 25.53,97.92 25.53,116.84 40.64,131.95 v1(179.54,131.95)
  BOTTOM w0.165: v1(179.54,131.95) J1.109 ; J4.73 v1(29.41,91.62)
CONN_G1: length 192.1
  LAYER3 w0.124: v1(29.91,91.12) 29.91,94.42 26.35,97.98 26.35,115.63 41.78,131.06 v1(179.04,131.06)
  BOTTOM w0.165: J4.75 v1(29.91,91.12) ; v1(179.04,131.06) J1.111
CONN_G2: length 191.6
  LAYER3 w0.124: v1(178.69,129.92) 42.67,129.92 27.05,114.3 27.05,98.81 31.37,94.49 31.37,92.84 30.91,92.38 v1(30.91,91.39)
  BOTTOM w0.165: v1(178.69,129.92) 178.69,130.41 178.54,130.56 J1.113 ; J4.79 v1(30.91,91.39)
CONN_G3: length 191.7
  LAYER3 w0.124: v1(31.62,91.57) 31.95,91.9 31.95,94.79 27.81,98.93 27.81,112.52 44.07,128.78 178.18,128.78 v1(178.82,128.14)
  BOTTOM w0.165: J1.115 178.04,128.92 v1(178.82,128.14) ; v1(31.62,91.57) 31.41,91.35 J4.81
CONN_G4: length 188.2
  LAYER3 w0.124: v1(176.91,128.27) 45.33,128.27 28.57,111.51 28.57,99.19 33.4,94.36 33.4,92.08 v1(32.41,91.08)
  BOTTOM w0.165: J1.117 177.54,128.9 v1(176.91,128.27) ; J4.85 v1(32.41,91.08)
CONN_G5: length 186.2
  LAYER3 w0.124: v1(176.02,127.51) 175.69,127.18 47.04,127.18 29.21,109.35 29.21,99.57 34.16,94.61 34.16,92.03 v1(33.32,91.19)
  BOTTOM w0.165: J1.119 177.04,131.58 176.02,130.56 v1(176.02,127.51) ; J4.87 32.91,90.77 v1(33.32,91.19)
CONN_LATA: length 196.7
  LAYER3 w0.124: v1(180.97,134.24) 179.59,134.24 178.7,133.34 38.73,133.34 23.88,118.49 23.88,97.79 26.8,94.87 26.8,92.33 v1(27.3,91.82)
  BOTTOM w0.165: J1.105 180.54,134.67 v1(180.97,134.24) ; v1(27.3,91.82) 27.3,91.44 27.91,90.84 J4.67
CONN_LATB: length 195.4
  LAYER3 w0.124: v1(28.41,91.1) 28.41,91.65 27.81,92.25 27.81,94.74 24.64,97.92 24.64,117.73 39.5,132.59 179.83,132.59 v1(180.34,133.1)
  BOTTOM w0.165: J4.69 v1(28.41,91.1) ; J1.107 180.04,133.88 180.34,133.59 v1(180.34,133.1)
DA0N: length 161.3
  TOP w0.114: J2.165 222.49,33.96 222.4,34.06 219.2,34.06 219.07,33.93 219.07,14.78 218.77,14.48 113.14,14.48 112.84,14.77 112.84,18.88 112.72,19.01 112.19,19.01 112.06,18.88 112.06,14.78 111.76,14.48 111,14.48 110.69,14.78 110.69,19.86 110.36,20.19 101.22,20.19 100.81,20.61 100.81,22.51 100.57,22.75 99.55,22.75 v1(99.07,22.26)
  BOTTOM w0.114: v1(99.07,22.26) J3.C10
DA0P: length 161.3
  TOP w0.114: J2.163 222.49,34.46 222.4,34.36 219.08,34.36 218.77,34.06 218.77,14.91 218.64,14.78 113.26,14.78 113.15,14.9 113.15,19.01 112.84,19.32 112.07,19.32 111.76,19.01 111.76,14.91 111.63,14.78 111.12,14.78 111,14.91 111,19.99 110.49,20.5 101.35,20.5 101.11,20.73 101.11,22.64 100.7,23.05 99.55,23.05 v1(99.07,23.53)
  BOTTOM w0.114: v1(99.07,23.53) J3.C11
DA1N: length 161.8
  TOP w0.114: v1(100.34,23.53) 100.82,24.01 101.8,24.01 102.11,23.7 102.11,21.84 102.49,21.46 114.17,21.46 114.55,21.08 114.55,16.38 114.86,16.08 115.82,16.08 116.13,16.38 116.13,20.89 116.26,21.02 116.97,21.02 117.09,20.89 117.09,16.38 117.4,16.08 118.46,16.08 118.75,16.37 118.75,17.27 118.88,17.4 119.19,17.4 119.32,17.27 119.32,16.37 119.61,16.08 215.34,16.08 216.18,16.91 216.18,34.77 216.97,35.56 222.4,35.56 222.49,35.46 J2.159
  BOTTOM w0.114: v1(100.34,23.53) J3.D11
DA1P: length 161.8
  TOP w0.114: v1(100.34,24.8) 100.83,24.31 101.92,24.31 102.41,23.83 102.41,21.97 102.62,21.77 114.3,21.77 114.86,21.21 114.86,16.51 114.99,16.38 115.7,16.38 115.82,16.51 115.82,21.02 116.13,21.32 117.09,21.32 117.4,21.02 117.4,16.51 117.53,16.38 118.33,16.38 118.44,16.5 118.44,17.4 118.75,17.7 119.32,17.7 119.63,17.4 119.63,16.5 119.74,16.38 215.21,16.38 215.87,17.04 215.87,34.9 216.84,35.86 222.4,35.86 222.49,35.96 J2.157
  BOTTOM w0.114: v1(100.34,24.8) J3.D12
